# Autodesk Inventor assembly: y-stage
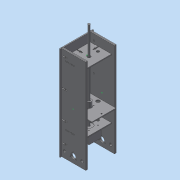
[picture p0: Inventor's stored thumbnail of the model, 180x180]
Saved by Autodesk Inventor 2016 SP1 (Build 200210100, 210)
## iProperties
Created: 2016-06
Part Number: y-stage
Document SubType Name: Assembly
Designer: Mohamed A.
Author: Mohamed A.
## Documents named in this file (9)
- C:\Users\Mohamed\Documents\inventor\machine_design\y-stage\y-stage.iam
- C:\Users\Mohamed\Documents\inventor\machine_design\y-stage\side.ipt
- C:\Users\Mohamed\Documents\inventor\machine_design\y-stage\back.ipt
- C:\Users\Mohamed\Documents\inventor\machine_design\stepper\body-box.ipt
- C:\Users\Mohamed\Documents\inventor\machine_design\y-stage\stepper-mount.ipt
- C:\Users\Mohamed\Documents\inventor\machine_design\y-stage\top.ipt
- C:\Users\Mohamed\Documents\inventor\machine_design\stepper\nut.ipt
- C:\Users\Mohamed\Documents\inventor\machine_design\y-stage\wire-holder-bottom.ipt
- C:\Users\Mohamed\Documents\inventor\machine_design\y-stage\side_outer.ipt
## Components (10 placed, 8 different names)
1. side:1 — Flush:1, Flush:2, Mate:4, Mate:7, Mate:10, Flush:12, Flush:13
2. side:2 — Flush:1, Flush:2, Flush:3, Flush:4, Mate:3, Mate:9, Flush:10, Flush:11
3. back:1 — Flush:3, Flush:4, Mate:1, Mate:2, Flush:5, Flush:7, Flush:9, Flush:14
4. body-box:1 — Mate:1, Mate:2, Mate:3, Mate:4, Flush:5, Mate:5, Cylindrical:1
5. stepper-mount:1 — Flush:7, Mate:5, Mate:6, Angle:2
6. top:1 — Flush:9, Mate:6
7. nut:1 — Cylindrical:1, Mate:8, Angle:1
8. wire-holder-bottom:1 — Mate:7, Mate:8, Angle:1, Angle:2
9. side_outer:1 — Mate:10, Flush:12, Flush:13, Flush:14
10. side_outer:2 — Mate:9, Flush:10, Flush:11
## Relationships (25: Flush 12, Mate 10, Angle 2, CylindricalJoint 1)
- Flush:1: side:1 ↔ side:2
- Flush:2: side:1 ↔ side:2
- Flush:3: side:2 ↔ back:1
- Flush:4: side:2 ↔ back:1
- Mate:1: back:1 ↔ body-box:1
- Mate:2: back:1 ↔ body-box:1
- Mate:3: side:2 ↔ body-box:1
- Mate:4: side:1 ↔ body-box:1
- Flush:5: back:1 ↔ body-box:1
- Flush:7: back:1 ↔ stepper-mount:1
- Mate:5: body-box:1 ↔ stepper-mount:1
- Flush:9: back:1 ↔ top:1
- Mate:6: stepper-mount:1 ↔ top:1
- Cylindrical:1: body-box:1 ↔ nut:1
- Mate:7: side:1 ↔ wire-holder-bottom:1
- Mate:8: nut:1 ↔ wire-holder-bottom:1
- Angle:1: nut:1 ↔ wire-holder-bottom:1
- Angle:2: stepper-mount:1 ↔ wire-holder-bottom:1
- Mate:9: side:2 ↔ side_outer:2
- Flush:10: side:2 ↔ side_outer:2
- Flush:11: side:2 ↔ side_outer:2
- Mate:10: side:1 ↔ side_outer:1
- Flush:12: side:1 ↔ side_outer:1
- Flush:13: side:1 ↔ side_outer:1
- Flush:14: back:1 ↔ side_outer:1
